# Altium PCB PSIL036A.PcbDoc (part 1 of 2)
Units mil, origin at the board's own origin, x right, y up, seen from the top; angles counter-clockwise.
Board outline 2820.01 x 3610.03 mil, 2 copper layers (Top Layer, Bottom Layer), stack 62 mil thick; 102 components, 95 nets, 316 pads, 73 vias.
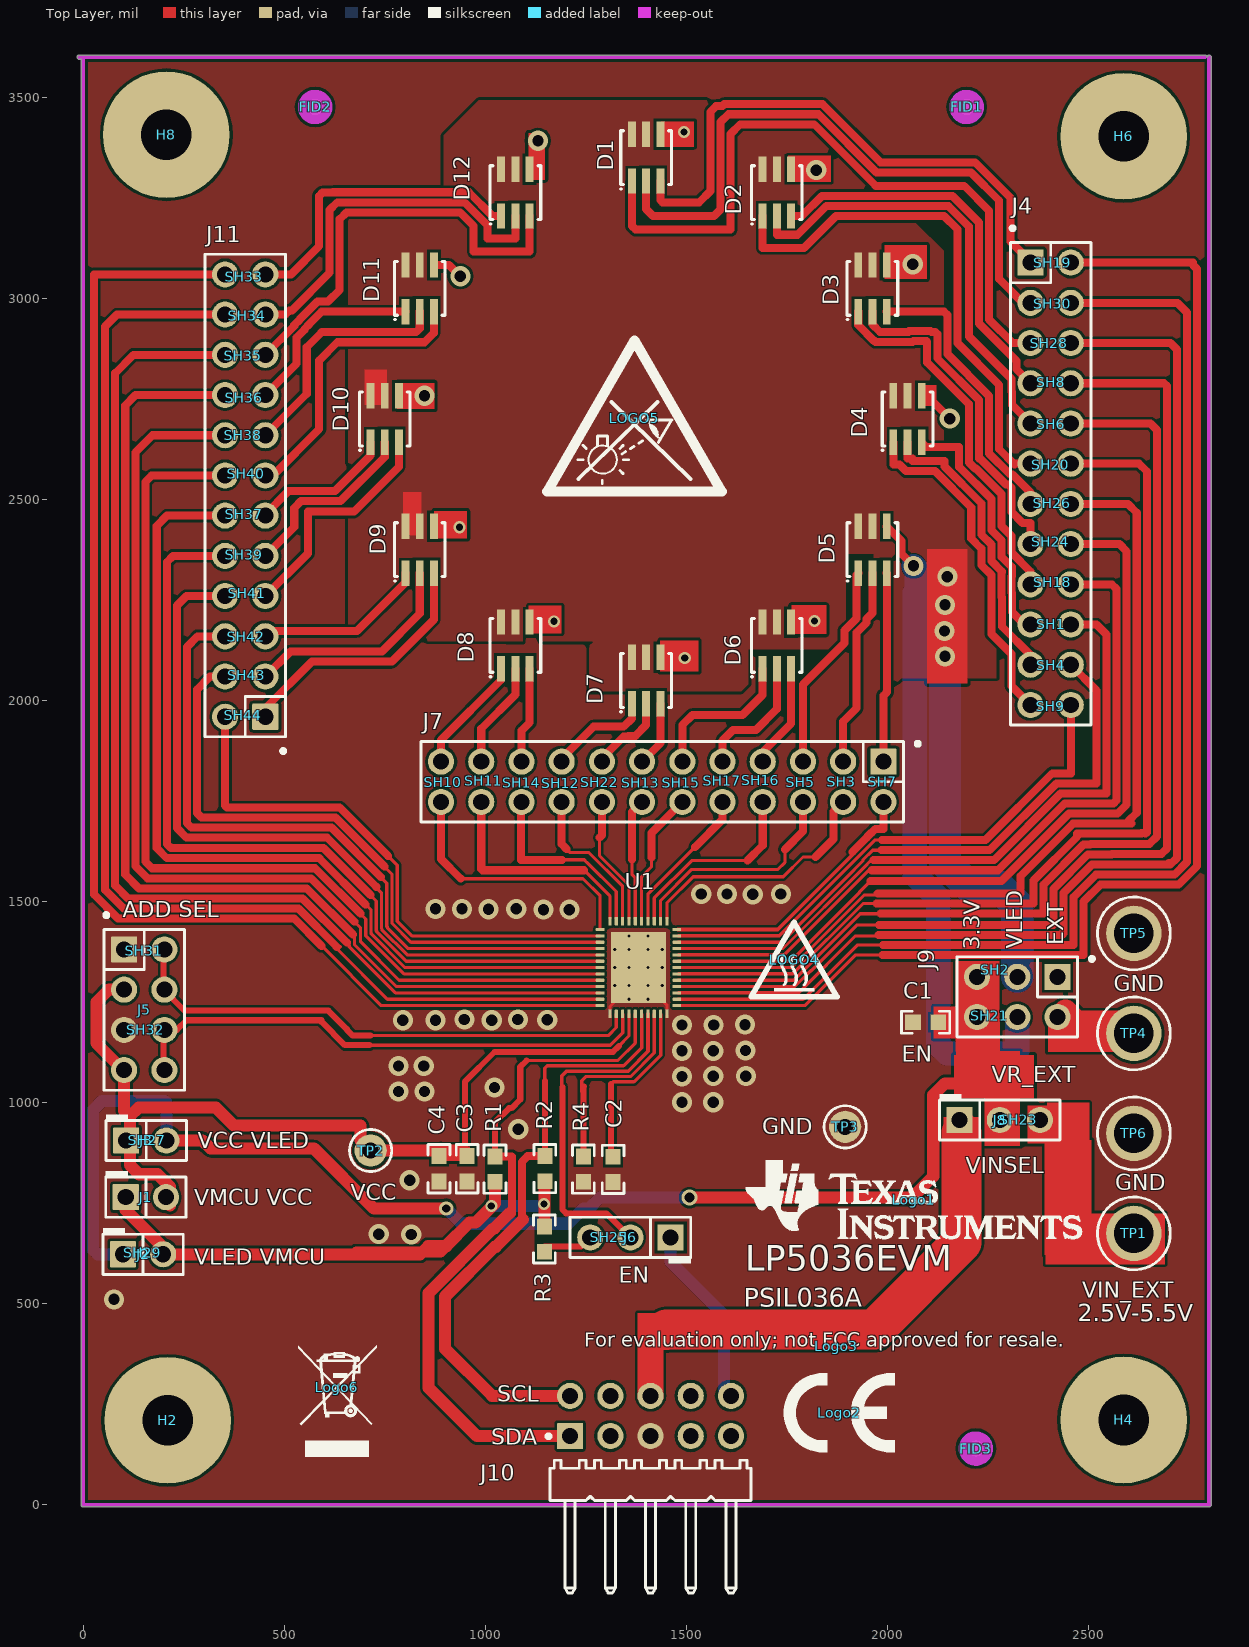
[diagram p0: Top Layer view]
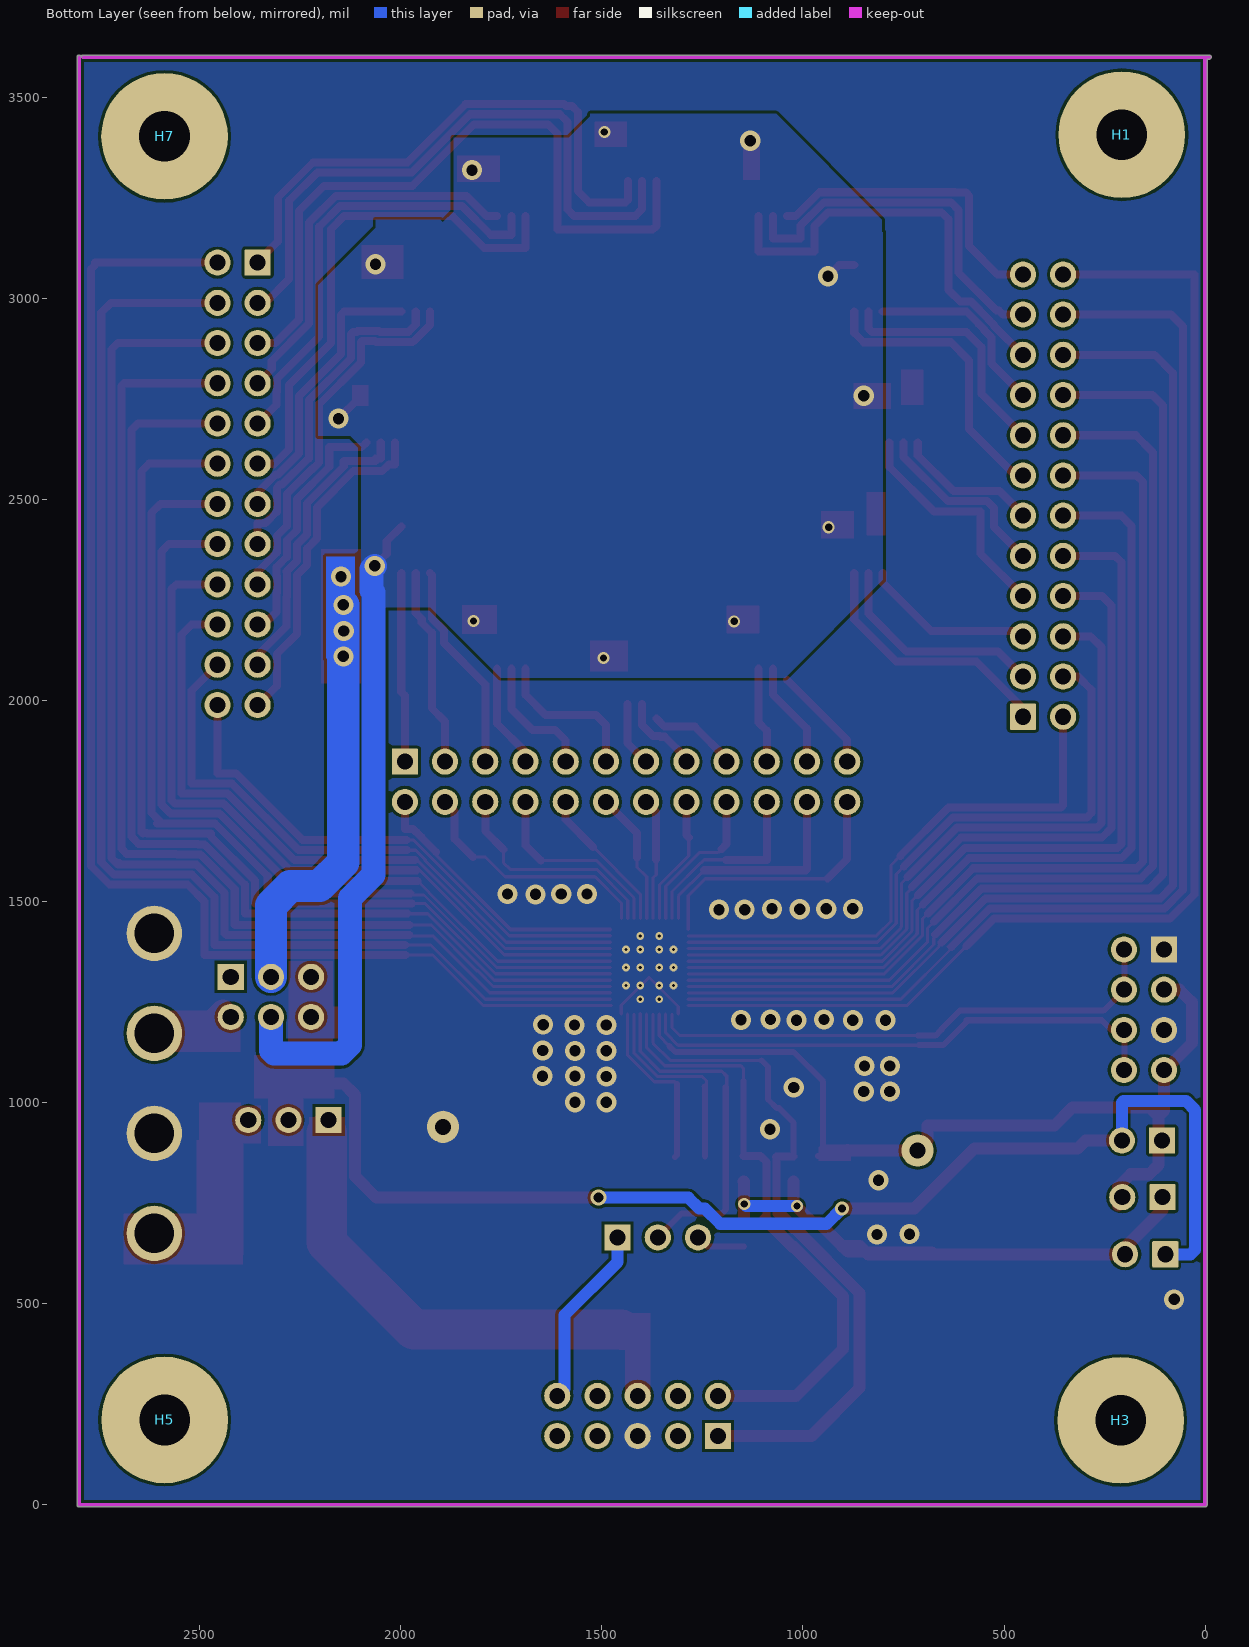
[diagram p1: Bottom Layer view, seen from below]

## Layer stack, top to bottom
Top Solder: solder mask 0.4, Solder Resist, Dk 3.5
Top Layer: signal copper 1.4
Dielectric1: core 59.2, FR-4, Dk 4.8
Bottom Layer: signal copper 1.4
Bottom Solder: solder mask 0.4, Solder Resist, Dk 3.5

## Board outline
-5.02,0 -5.02,3594.98 -10,3594.98 cw(c-10,3600) -10,3605.02 2790,3605.02 cw(c2790,3600) 2794.01,3603.02 2795.99,3603.02 ccw(c2800,3600) 2795,3600.39 ccw(c2790,3600) 2794.01,3603.02 2795.99,3603.02 cw(c2800,3600) 2805.02,3600 2805.02,0 cw(c2800,0) 2800,-5.01 0,-5.01 cw(c0,0)

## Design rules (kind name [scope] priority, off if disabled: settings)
AcuteAngle [All] p1: minimum=4.50000000000000E+0001 checktracksonly=FALSE
AssemblyTestPointUsage [All] p1: valid=2
Clearance Clearance_Keepouts [((IsTrack Or IsArc) And Not InPoly) And IsFree and IsKeepOut vs ((IsTrack Or IsArc) And Not InPoly) And IsFree and IsKeepOut] p1: gap=0 ignorepadtopadclearanceinfootprint=FALSE
Clearance Clearance_Poly [InPolygon] p2: gap=7 ignorepadtopadclearanceinfootprint=FALSE except(0: Arc-Hole Track-Hole SMDPad-Hole THPad-Hole Via-Hole Fill-Hole Poly-Hole Region-Hole Text-Hole)
Clearance [All] p3: gap=5 ignorepadtopadclearanceinfootprint=FALSE except(0: Arc-Hole Track-Hole SMDPad-Hole THPad-Hole Via-Hole Fill-Hole Poly-Hole Region-Hole Text-Hole)
ComponentClearance ComponentClearance_MountingHoles_FiducialMarks [InComponentClass('Mounting Holes') vs InComponentClass('FiducialMark')] p1: gap=50 collisioncheckmode=3 verticalgap=10 showdistances=FALSE
ComponentClearance [InComponent('Logo1') vs InComponent('Logo4')] p2: gap=0 collisioncheckmode=3 verticalgap=0 showdistances=FALSE
ComponentClearance ComponentClearance_Shunt [InComponentClass('Header') vs InComponentClass('Shunt')] p3: gap=0 collisioncheckmode=3 verticalgap=0 showdistances=FALSE
ComponentClearance ComponentClearance_Shunt_1 [InComponentClass('Header') vs InComponentClass('Shunt')] p4: gap=0 collisioncheckmode=3 verticalgap=0 showdistances=FALSE
ComponentClearance ComponentClearance_Logo [InComponentClass('Logo')] p5: gap=30 collisioncheckmode=3 verticalgap=10 showdistances=FALSE
ComponentClearance ComponentClearance_ScrewToNut [(HasFootprint('NY PMS 440 0025 PH')) vs (HasFootprint('Keystone_1902C'))] p6: gap=5 collisioncheckmode=3 verticalgap=10 showdistances=FALSE
ComponentClearance ComponentClearance_ScrewToNut_1 [(HasFootprint('NY PMS 440 0025 PH')) vs (HasFootprint('Keystone_2204'))] p7: gap=0 collisioncheckmode=3 verticalgap=0 showdistances=FALSE
ComponentClearance ComponentClearance_MountingHoles [InComponentClass('Mounting Holes')] p8: gap=20 collisioncheckmode=3 verticalgap=100000 showdistances=FALSE
ComponentClearance ComponentClearance_SmallPassives [HasFootprint('0201*') or HasFootprint('0402*') or HasFootprint('0508') or HasFootprint('0603*') or HasFootprint('0612') or HasFootprint('0805*') or HasFootprint('0815*') or HasFootprint('0830*') or HasFootprint('1206*') or HasFootprint('1210*') or HasFootprint('1808*') or HasFootprint('1812*') or HasFootprint('1825*') or HasFootprint('2010*') or HasFootprint('2220*') or HasFootprint('2225*') or HasFootprint('2512*') or HasFootprint('2728*') or HasFootprint('3518*') vs HasFootprint('0201*') or HasFootprint('0402*') or HasFootprint('0508') or HasFootprint('0603*') or HasFootprint('0612') or HasFootprint('0805*') or HasFootprint('0815*') or HasFootprint('0830*') or HasFootprint('1206*') or HasFootprint('1210*') or HasFootprint('1808*') or HasFootprint('1812*') or HasFootprint('1825*') or HasFootprint('2010*') or HasFootprint('2220*') or HasFootprint('2225*') or HasFootprint('2512*') or HasFootprint('2728*') or HasFootprint('3518*')] p9: gap=14.96 collisioncheckmode=3 verticalgap=10 showdistances=FALSE
ComponentClearance ComponentClearance_THtoSMT [IsThruComponent vs IsSMTComponent] p10: gap=40 collisioncheckmode=3 verticalgap=30 showdistances=FALSE
ComponentClearance ComponentClearance_THtoTH [IsThruComponent vs IsThruComponent] p11: gap=30 collisioncheckmode=3 verticalgap=30 showdistances=FALSE
ComponentClearance ComponentClearance_THtoTH_1 [InComponent('J8A') vs InComponent('J8B')] p12: gap=0 collisioncheckmode=3 verticalgap=0 showdistances=FALSE
ComponentClearance ComponentClearance_THtoTH_2 [InComponent('J8B') vs InComponent('J8C')] p13: gap=0 collisioncheckmode=3 verticalgap=0 showdistances=FALSE
DiffPairsRouting [All] p1: maxlimit=100 minlimit=10 mostfreqgap=10 toplayer_minwidth=15 toplayer_maxwidth=15 toplayer_prefwidth=15 bottomlayer_minwidth=15 bottomlayer_maxwidth=15 bottomlayer_prefwidth=15 maxuncoupledlength=1000
FabricationTestPointUsage TestPointUsage [All] p1: valid=2 allowmultiple=FALSE
FabricationTestpoint Testpoint [All] p1: side=3 testpointundercomponent=TRUE minsize=40 maxsize=100 preferedsize=60 minholesize=0 maxholesize=40 preferedholesize=32 testpointgrid=1 allowsidetop=TRUE allowsidebottom=TRUE usegrid=TRUE gridtolerance=0.01
FanoutControl Fanout_LCC [IsLCC] p1: bgadir=Out bgaviamode=Centered fanoutstyle=Auto fanoutdirection=Alternating viagrid=1 // Fanout_LCC (Default Rule)
FanoutControl Fanout_BGA [IsBGA] p2: bgadir=Out bgaviamode=Centered fanoutstyle=Auto fanoutdirection=Alternating viagrid=1 // Fanout_BGA (Default Rule)
FanoutControl Fanout_Default [All] p4: bgadir=Out bgaviamode=Centered fanoutstyle=Auto fanoutdirection=Alternating viagrid=1 // Fanout_Default (Default Rule)
FanoutControl Fanout_Small [(CompPinCount < 5)] p5: bgadir=Out bgaviamode=Centered fanoutstyle=Auto fanoutdirection=OutThenIn viagrid=1 // Fanout_Small (Default Rule)
HoleSize [All] p1: absolutevalues=TRUE maxlimit=251 minlimit=7.87 maxpercent=80.000 minpercent=20.000
MinimumAnnularRing MinimumAnnularRing_ThermalPadVias [IsVia and InAnyComponent] p1: minimumring=5.91
MinimumAnnularRing [All] p2: minimumring=6
MinimumSolderMaskSliver MinimumSolderMaskSliver_Logo [InComponentClass('Logo') vs InComponentClass('Logo')] p1: minsoldermaskwidth=0.7
MinimumSolderMaskSliver [All] p2: minsoldermaskwidth=3.94
PlaneClearance [InNet('SW')] p1: clearance=7
PlaneClearance PlaneClearance_1 [All] p2: clearance=20
PlaneConnect [InNet('SW')] p1: planeconnectstyle=Direct reliefexpansion=10 reliefentries=4 reliefconductorwidth=10 reliefairgap=10
PlaneConnect PlaneConnect_1 [All] p2: planeconnectstyle=Relief reliefexpansion=10 reliefentries=4 reliefconductorwidth=10 reliefairgap=10
PolygonConnect [InNet('SW') vs HasFootprint('DFE252012C')] p1: connectstyle=Direct reliefconductorwidth=10 reliefentries=4 polygonreliefangle="90 Angle" airgapwidth=10
PolygonConnect PolygonConnect_3 [InNet('GND') vs (HasFootprint('0603') OR HasFootprint('1210_280') OR IsVia)] p2: connectstyle=Direct reliefconductorwidth=10 reliefentries=4 polygonreliefangle="90 Angle" airgapwidth=10
PolygonConnect PolygonConnect_2 [InNet('VIN2') vs (HasFootprint('0603') OR HasFootprint('1210_280') OR IsVia)] p3: connectstyle=Direct reliefconductorwidth=10 reliefentries=4 polygonreliefangle="90 Angle" airgapwidth=10
PolygonConnect PolygonConnect_1 [All] p4: connectstyle=Direct reliefconductorwidth=30 reliefentries=4 polygonreliefangle="90 Angle" airgapwidth=10
RoutingVias ThermalPadVias [IsVia and InAnyComponent] p1: holewidth=7.87 width=19.68 viastyle="Through Hole" minholewidth=7.87 minwidth=19.68 maxholewidth=12.99 maxwidth=23.62
RoutingVias [All] p2: holewidth=16 width=34 viastyle="Through Hole" minholewidth=8 minwidth=20 maxholewidth=40 maxwidth=65
SilkToBoardRegionClearance [Not ((IsComment or IsDesignator) And (Hide <> 'False')) and not InRegion(1000,500,4000,800)] p1:
SilkToSilkClearance SilkToSilkClearance_Pb-FreeLogo [(HasFootprint('Pb-Free_Overlay_Medium') OR HasFootprint('Pb-Free_Overlay_Small')) vs (HasFootprint('Pb-Free_Overlay_Medium') OR HasFootprint('Pb-Free_Overlay_Small'))] p1: silktosilkclearance=3
SilkToSilkClearance [OnLayer('Bottom Overlay')] p2: silktosilkclearance=3
SilkToSilkClearance SilkToSilkClearance_1 [OnLayer('Top Overlay')] p3: silktosilkclearance=3
SilkToSolderMaskClearance SilkToComponentPadClearance_1 [IsPad and InAnycomponent vs OnLayer('Bottom Overlay')] p1: minsilkscreentomaskgap=0 clearancetoexposedcopper=TRUE
SilkToSolderMaskClearance SilkToComponentPadClearance_2 [IsVia vs OnLayer('Bottom Overlay')] p2: minsilkscreentomaskgap=0 clearancetoexposedcopper=TRUE
SilkToSolderMaskClearance SilkToComponentPadClearance [IsPad and InAnycomponent] p3: minsilkscreentomaskgap=4 clearancetoexposedcopper=TRUE
SilkToSolderMaskClearance "Silk to Solder Mask Opening" [All] p4: minsilkscreentomaskgap=4 clearancetoexposedcopper=FALSE
SolderMaskExpansion [All] p1: expansion=1.97
Width [All] p1: maxlimit=100 minlimit=6 preferedwidth=7 checkconnectedcopper=TRUE
14 further rules are at their usual default settings.

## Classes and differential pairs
component class FiducialMark: FID1 FID2 FID3
component class PSIL036A_Hardware: FID1 FID2 FID3 H1 H2 H3 H4 H5 H6 H7 H8 Logo1 Logo2 Logo3 LOGO4 LOGO5 Logo6 SH1 SH2 SH3 SH4 SH5 SH6 SH7 SH8 SH9 SH10 SH11 SH12 SH13 SH14 SH15 SH16 SH17 SH18 SH19 SH20 SH21 SH22 SH23 SH24 SH25 SH26 SH27 SH28 SH29 SH30 SH31 SH32 SH33 SH34 SH35 SH36 SH37 SH38 SH39 SH40 SH41 SH42 SH43 SH44 ZZ2 ZZ3 ZZ4
component class Header: J1 J2 J3 J4 J5 J6 J7 J8 J9 J10 J11 J15
component class PSIL036A_sh: C1 C2 C3 C4 D1 D2 D3 D4 D5 D6 D7 D8 D9 D10 D11 D12 J1 J2 J3 J4 J5 J6 J7 J8 J9 J10 J11 J15 J101 L100 R1 R2 R3 R4 R13 SH-J10 TP1 TP2 TP3 TP4 TP5 TP6 U1 VOUT
component class AssemblyNote: ZZ2 ZZ3 ZZ4
component class Logo: Logo1
component class Shunt: SH1 SH2 SH3 SH4 SH5 SH6 SH7 SH8 SH9 SH10 SH11 SH12 SH13 SH14 SH15 SH16 SH17 SH18 SH19 SH20 SH21 SH22 SH23 SH24 SH25 SH26 SH27 SH28 SH29 SH30 SH31 SH32 SH33 SH34 SH35 SH36 SH37 SH38 SH39 SH40 SH41 SH42 SH43 SH44 SH-J9
component class "Mounting Holes": H2 H4 H6 H8

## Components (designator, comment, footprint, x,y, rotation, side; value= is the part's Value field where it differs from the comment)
C1 "C1608JB0J106K080AB" 0603 2095,1200 r180 top value=10uF
C2 "06033C105KAT2A" 0603 1318,834 r270 top value=1uF
C3 "06033C105KAT2A" 0603 955,835.7 r270 top value=1uF
C4 "0603YC104JAT2A" 0603 885,835.7 r270 top value=0.1uF
D1 "ASMT-YTC2-0AA02" Avago_ASMT-YTC2-0AA02 1400,3350 r90 top value=Rgb
D2 "ASMT-YTC2-0AA02" Avago_ASMT-YTC2-0AA02 1725,3262.9 r90 top value=Rgb
D3 "ASMT-YTC2-0AA02" Avago_ASMT-YTC2-0AA02 1962.9,3025 r90 top value=Rgb
D4 "ASMT-YTC2-0AA02" Avago_ASMT-YTC2-0AA02 2050,2700 r90 top value=Rgb
D5 "ASMT-YTC2-0AA02" Avago_ASMT-YTC2-0AA02 1962.9,2375 r90 top value=Rgb
D6 "ASMT-YTC2-0AA02" Avago_ASMT-YTC2-0AA02 1725,2137.1 r90 top value=Rgb
D7 "ASMT-YTC2-0AA02" Avago_ASMT-YTC2-0AA02 1400,2050 r90 top value=Rgb
D8 "ASMT-YTC2-0AA02" Avago_ASMT-YTC2-0AA02 1075,2137.1 r90 top value=Rgb
D9 "ASMT-YTC2-0AA02" Avago_ASMT-YTC2-0AA02 837.1,2375 r90 top value=Rgb
D10 "ASMT-YTC2-0AA02" Avago_ASMT-YTC2-0AA02 750,2700 r90 top value=Rgb
D11 "ASMT-YTC2-0AA02" Avago_ASMT-YTC2-0AA02 837.1,3025 r90 top value=Rgb
D12 "ASMT-YTC2-0AA02" Avago_ASMT-YTC2-0AA02 1075,3262.9 r90 top value=Rgb
FID1 "Fiducial" Fiducial10-20 2197,3476 r0 top
FID2 "Fiducial" Fiducial10-20 577,3476 r0 top
FID3 "Fiducial" Fiducial10-20 2220,140 r0 top
H1 "1902C" Keystone_1902C 207,3407 r180 bottom
H2 "NY PMS 440 0025 PH" "NY PMS 440 0025 PH" 210,210 r0 top
H3 "1902C" Keystone_1902C 210,210 r180 bottom
H4 "NY PMS 440 0025 PH" "NY PMS 440 0025 PH" 2587.47,211 r0 top
H5 "1902C" Keystone_1902C 2587.47,211 r0 bottom
H6 "NY PMS 440 0025 PH" "NY PMS 440 0025 PH" 2587.53,3403 r0 top
H7 "1902C" Keystone_1902C 2587.53,3403 r180 bottom
H8 "NY PMS 440 0025 PH" "NY PMS 440 0025 PH" 207,3407 r0 top
J1 "VMCU VCC" TSW-102-07-G-S 156,765 r0 top
J2 "VLED VMCU" TSW-102-07-G-S 149,623 r0 top
J3 "VCC VLED" TSW-102-07-G-S 157,906 r0 top
J4 "TSW-112-07-G-D" TSW-112-07-G-D 2405.99,2539 r270 top
J5 "ADD SEL" TSW-104-07-G-D 152,1231 r270 top
J6 "EN" TSW-103-07-G-S 1361,665 r180 top
J7 "TSW-112-07-G-D" TSW-112-07-G-D 1440,1798 r180 top
J8 "VINSEL" TSW-103-07-G-S 2279.51,956.91 r0 top
J9 "" TSW-103-07-G-D 2323,1263 r180 top
J10 "TSW-105-08-G-D-RA" Samtec_TSW-105-08-G-D-RA 1411,221 r0 top
J11 "TSW-112-07-G-D" TSW-112-07-G-D 403,2509.76 r90 top
Logo1 "Texas Instruments" TI_Stacked_Overlay_Small 2065.78,758.88 r0 top
Logo2 "CE Mark" CE_Mark_5mm 1880,229 r0 top (schematic designator LOGO2)
Logo3 "FCC disclaimer" FCC_disclaimer 1873,394 r0 top
LOGO4 "CAUTION HOT SURFACE" IEC_HotSurface_Small 1768,1356 r0 top
LOGO5 "LED WARNING" LED_Warning 1371,2702 r0 top
Logo6 "WEEE logo" WEEE_Minimum 631,292 r0 top
R1 "CRCW06034K70JNEA" 0603 1024,835 r270 top value=4.7k
R2 "CRCW06034K70JNEA" 0603 1148,836 r270 top value=4.7k
R3 "CRCW06034K70JNEA" 0603 1147,661 r90 top value=4.7k
R4 "RC0603FR-073K57L" 0603 1244,835 r90 top value=3.57k
SH1 "" SPC02SYAN 2408,2190 r0 top value=1x2
SH2 "" SPC02SYAN 2268,1330 r0 top value=1x2
SH3 "" SPC02SYAN 1886,1798 r270 top value=1x2
SH4 "" SPC02SYAN 2408,2088 r0 top value=1x2
SH5 "" SPC02SYAN 1784,1797 r270 top value=1x2
SH6 "" SPC02SYAN 2408,2687 r0 top value=1x2
SH7 "" SPC02SYAN 1988,1798 r270 top value=1x2
SH8 "" SPC02SYAN 2408,2792 r0 top value=1x2
SH9 "" SPC02SYAN 2406,1986 r0 top value=1x2
SH10 "" SPC02SYAN 895,1797 r90 top value=1x2
SH11 "" SPC02SYAN 996,1800 r90 top value=1x2
SH12 "" SPC02SYAN 1188,1794 r90 top value=1x2
SH13 "" SPC02SYAN 1387,1796 r90 top value=1x2
SH14 "" SPC02SYAN 1091,1795 r90 top value=1x2
SH15 "" SPC02SYAN 1487,1795 r90 top value=1x2
SH16 "" SPC02SYAN 1685,1802 r90 top value=1x2
SH17 "" SPC02SYAN 1589,1801 r90 top value=1x2
SH18 "" SPC02SYAN 2411,2294 r180 top value=1x2
SH19 "" SPC02SYAN 2411,3089 r180 top value=1x2
SH20 "" SPC02SYAN 2406,2586 r180 top value=1x2
SH21 "" SPC02SYAN 2254,1216 r180 top value=1x2
SH22 "" SPC02SYAN 1285,1797 r90 top value=1x2
SH23 "" SPC02SYAN 2327,958 r180 top value=1x2
SH24 "" SPC02SYAN 2406,2395 r180 top value=1x2
SH25 "" SPC02SYAN 1308,665 r180 top value=1x2
SH26 "" SPC02SYAN 2410,2490 r180 top value=1x2
SH27 "" SPC02SYAN 160,907 r180 top value=1x2
SH28 "" SPC02SYAN 2403,2889 r180 top value=1x2
SH29 "" SPC02SYAN 148,627 r180 top value=1x2
SH30 "" SPC02SYAN 2411,2987 r180 top value=1x2
SH31 "" SPC02SYAN 152,1378 r180 top value=1x2
SH32 "" SPC02SYAN 156,1181 r180 top value=1x2
SH33 "" SPC02SYAN 401,3054 r180 top value=1x2
SH34 "" SPC02SYAN 408,2957 r180 top value=1x2
SH35 "" SPC02SYAN 398,2857 r180 top value=1x2
SH36 "" SPC02SYAN 401,2753 r180 top value=1x2
SH37 "" SPC02SYAN 401,2463 r180 top value=1x2
SH38 "" SPC02SYAN 398,2660 r180 top value=1x2
SH39 "" SPC02SYAN 401,2363 r180 top value=1x2
SH40 "" SPC02SYAN 405,2564 r180 top value=1x2
SH41 "" SPC02SYAN 408,2267 r180 top value=1x2
SH42 "" SPC02SYAN 405,2159 r180 top value=1x2
SH43 "" SPC02SYAN 407,2063 r180 top value=1x2
SH44 "" SPC02SYAN 398,1963 r180 top value=1x2
TP1 "VIN_EXT" Keystone1502-2 2613,675 r0 top
TP2 "VCC" Keystone5000 715,881 r90 top
TP3 "GND" Keystone5001 1895,940 r0 top
TP4 "VR_EXT" Keystone1502-2 2613,1172.33 r0 top
TP5 "GND" Keystone1502-2 2613,1421 r0 top
TP6 "GND" Keystone1502-2 2613,923.67 r0 top
U1 "LP5036RJVR" RJV0046A 1381,1336 r180 top
ZZ2 "These assemblies are ESD sensitive, ESD precautions shall be observed." AssemblyNote -285.77,3783.99 r0 top
ZZ3 "These assemblies must be clean and free from flux and all contaminants. Use of no clean flux is not acceptable." AssemblyNote -285.77,3683.99 r0 top
ZZ4 "These assemblies must comply with workmanship standards IPC-A-610 Class 2, unless otherwise specified." AssemblyNote -293,3885 r0 top

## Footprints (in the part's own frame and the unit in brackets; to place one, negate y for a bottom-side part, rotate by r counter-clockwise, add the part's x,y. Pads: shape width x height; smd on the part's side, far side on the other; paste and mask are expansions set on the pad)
0603 [mm] "0603 from SM-752 data"
  rect 1x0.95 smd: 1(-0.8,0) 2(0.8,0)
  silkscreen extent -1.52,-0.69 1.52,0.69, body extent -0.87,-0.47 0.87,0.47, height 1
AssemblyNote [mil] "Assembly Note"
Avago_ASMT-YTC2-0AA02 [mm] "Avago"
  rect 1.6x0.5 smd: 1(-1.475,0.9) 2(-1.475,0) 3(-1.475,-0.9) 4(1.475,-0.9) 5(1.475,0) 6(1.475,0.9)
  silkscreen extent -1.97,-1.6 1.7,1.6, body extent -1.7,-1.6 1.7,1.6, height 2
CE_Mark_5mm [mil] "Minimum text height for CE Mark"
  silkscreen extent -138,-98 138,98
FCC_disclaimer [mil]
Fiducial10-20 [mm]
  round 1 smd mask+0.5: 1(0,0)
  Top Layer keep-out circle w1.178: c0,0 r0.5
IEC_HotSurface_Small [mil]
  silkscreen extent -107,-93 107,92
Keystone1502-2 [mm] "Double Turret"
  round 3.5 hole 2.5: 1(0,0)
  silkscreen extent -2.3,-2.3 2.3,2.3, body extent -1.6,-1.6 1.59,1.6, height 5.62
Keystone5000 [mil] "For Keystone 500x miniature loop terminals"
  round 80 hole 40: 1(0,0)
  silkscreen extent -52,-52 52,52, body extent -49,-49 49,49, height 182
Keystone5001 [mil] "For Keystone 500x miniature loop terminals"
  round 80 hole 40: 1(0,0)
  silkscreen extent -52,-52 52,52, body extent -49,-49 49,49, height 182
Keystone_1902C [mil] "Hex Standoff, 4-40 threaded, nylon"
  round 1 on Mech4: 0(0,0)
  body extent -145,-126 146,126, height 501
LED_Warning [mil]
  silkscreen extent -217,-182 217,193
"NY PMS 440 0025 PH" [mm] "4-40 nylon screw and mounting hole"
  round 8 hole 3.2: 1(0,0)
  body extent -3.3,-3.3 3.3,3.3, height 2.69
RJV0046A [mm] "QFN, 46-Leads, Body 5x6mm, Pitch 0.4mm"
  rrect50% 0.55x0.2 smd: 1(-2.425,2.4) 2(-2.425,2) 3(-2.425,1.6) 4(-2.425,1.2) 5(-2.425,0.8) 6(-2.425,0.4) 7(-2.425,0) 8(-2.425,-0.4) 9(-2.425,-0.8) 10(-2.425,-1.2) 11(-2.425,-1.6) 12(-2.425,-2) 13(-2.425,-2.4) 24(2.425,-2.4) 25(2.425,-2) 26(2.425,-1.6) 27(2.425,-1.2) 28(2.425,-0.8) 29(2.425,-0.4) 30(2.425,0) 31(2.425,0.4) 32(2.425,0.8) 33(2.425,1.2) 34(2.425,1.6) 35(2.425,2) 36(2.425,2.4)
  rrect50% 0.2x0.55 smd: 14(-1.8,-2.925) 15(-1.4,-2.925) 16(-1,-2.925) 17(-0.6,-2.925) 18(-0.2,-2.925) 19(0.2,-2.925) 20(0.6,-2.925) 21(1,-2.925) 22(1.4,-2.925) 23(1.8,-2.925) 37(1.8,2.925) 38(1.4,2.925) 39(1,2.925) 40(0.6,2.925) 41(0.2,2.925) 42(-0.2,2.925) 43(-0.6,2.925) 44(-1,2.925) 45(-1.4,2.925) 46(-1.8,2.925)
  rrect3% 3.5x4.5 smd paste-4.5: 47(0,0)
  rrect11% 1x0.94 on Top Paste: ""(-1.2,1.71) ""(-1.2,-0.57) ""(-1.2,0.57) ""(-1.2,-1.71) ""(0,1.71) ""(0,0.57) ""(0,-0.57) ""(0,-1.71) ""(1.2,1.71) ""(1.2,-0.57) ""(1.2,0.57) ""(1.2,-1.71)
  body extent -2.5,-3 2.5,3, height 1
Samtec_TSW-105-08-G-D-RA [mm] "Samtec Right Angle Header"
  rrect6% 1.65x1.65 / inner rect 1.65x1.65 / far side rect 1.65x1.65 hole 1: 1(-5.08,-1.27)
  round 1.65 hole 1: 2(-5.08,1.27) 3(-2.54,-1.27) 4(-2.54,1.27) 5(0,-1.27) 6(0,1.27) 7(2.54,-1.27) 8(2.54,1.27) 9(5.08,-1.27) 10(5.08,1.27)
  silkscreen extent -6.57,-11.18 6.35,-1.16, body extent -6.35,-11.18 6.35,1.59, height 5.64
SPC02SYAN [mil] "SULLINS"
  round 1 on Mech3: 0(0,0)
  body extent -98,-47 99,47, height 366
TI_Stacked_Overlay_Small [mil]
  silkscreen extent -418,-98 418,98
TSW-102-07-G-S [mm] "Samtec 100mil, 1x2, 230 mil above insulator"
  rrect6% 1.65x1.65 hole 1.016: 1(-1.27,0)
  round 1.65 hole 1.016: 2(1.27,0)
  silkscreen extent -2.54,-1.27 2.54,1.65, body extent -2.54,-1.27 2.54,1.27, height 8.38
TSW-103-07-G-D [mm] "Samtec 100mil, 2x3, 230 mil above insulator"
  rect 1.65x1.65 hole 1.016: 1(-2.54,-1.27)
  round 1.65 hole 1.016: 2(-2.54,1.27) 3(0,-1.27) 4(0,1.27) 5(2.54,-1.27) 6(2.54,1.27)
  silkscreen extent -4.84,-2.54 3.81,2.54, body extent -3.81,-2.54 3.81,2.54, height 8.38
TSW-103-07-G-S [mm] "Samtec 100mil, 1x3, 230 mil above insulator"
  rect 1.65x1.65 hole 1.016: 1(-2.54,0)
  round 1.65 hole 1.016: 2(0,0) 3(2.54,0)
  silkscreen extent -3.81,-1.27 3.81,1.65, body extent -3.81,-1.27 3.81,1.27, height 8.38
TSW-104-07-G-D [mm] "Samtec 100mil, 2x4, 230 mil above insulator"
  rrect6% 1.65x1.65 hole 1.016: 1(-3.81,-1.27)
  round 1.65 hole 1.016: 2(-3.81,1.27) 3(-1.27,-1.27) 4(-1.27,1.27) 5(1.27,-1.27) 6(1.27,1.27) 7(3.81,-1.27) 8(3.81,1.27)
  silkscreen extent -6.1,-2.54 5.08,2.54, body extent -5.08,-2.54 5.08,2.54, height 8.38
TSW-112-07-G-D [mm] "Samtec 100mil, 2x12, 230 mil above insulator"
  rrect6% 1.65x1.65 hole 1.016: 1(-13.97,-1.27)
  round 1.65 hole 1.016: 2(-13.97,1.27) 3(-11.43,-1.27) 4(-11.43,1.27) 5(-8.89,-1.27) 6(-8.89,1.27) 7(-6.35,-1.27) 8(-6.35,1.27) 9(-3.81,-1.27) 10(-3.81,1.27) 11(-1.27,-1.27) 12(-1.27,1.27) 13(1.27,-1.27) 14(1.27,1.27) 15(3.81,-1.27) 16(3.81,1.27) 17(6.35,-1.27) 18(6.35,1.27) 19(8.89,-1.27) 20(8.89,1.27) 21(11.43,-1.27) 22(11.43,1.27) 23(13.97,-1.27) 24(13.97,1.27)
  silkscreen extent -16.26,-2.54 15.24,2.54, body extent -15.24,-2.54 15.24,2.54, height 8.38
WEEE_Minimum [mil] "WEEElie bin"
  silkscreen extent -95,-172 99,104

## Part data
C1: "CAP, CERM, 10 μF, 6.3 V, +/- 10%, JB, 0603", Cap_Case=0603, Manufacturer=TDK, Supplier Part Number 1=445-11185-1-ND, TempCo=JB, Tolerance_%=10, Value1=Unknown, Value2=6.3V, ValueDisplayed=10μF
C2 C3: "CAP, CERM, 1 μF, 25 V,+/- 10%, X7R, 0603", Cap_Case=0603, Manufacturer=AVX, Supplier Part Number 1=478-10046-1-ND, TempCo=X7R, Tolerance_%=10, Value2=25V, ValueDisplayed=1μF
C4: "CAP, CERM, 0.1 μF, 16 V,+/- 5%, X7R, 0603", Cap_Case=0603, Manufacturer=AVX, Supplier Part Number 1=478-3726-1-ND, TempCo=X7R, Tolerance_%=5, Value1="0.039 ohm", Value2=16V, ValueDisplayed=0.1μF
D1 D2 D3 D4 D5 D6 D7 D8 D9 D10 D11 D12: "LED, Rgb, SMD", Color=RGB, Manufacturer=Avago, Supplier Part Number 1=516-2513-1-ND, Value1=W, Value2=3.2V
FID1 FID2 FID3: "Fiducial mark.  There is nothing to buy or mount.", Manufacturer=N/A
H1 H3 H5 H7: "Standoff, Hex, 0.5\"L #4-40 Nylon", Manufacturer=Keystone, Supplier Part Number 1=36-1902C-ND
H2 H4 H6 H8: "Machine Screw, Round, #4-40 x 1/4, Nylon, Philips panhead", DigiKeyPartNumber=H542-ND, Manufacturer="B&F Fastener Supply"
J1 J2 J3: library part TSW-102-07-G-S, "Header, 100mil, 2x1, Gold, TH", Color=Black, Current_A=6.3, Manufacturer=Samtec, Supplier Part Number 1=SAM1029-02-ND, Voltage_V=550
J4 J7 J11: "Header, 100mil, 12x2, Gold, TH", Color=Black, Current_A=6.3, Manufacturer=Samtec, Supplier Part Number 1=SAM1028-12-ND, Voltage_V=550
J5: library part TSW-104-07-G-D, "Header, 100mil, 4x2, Gold, TH", Color=Black, Current_A=6.3, Manufacturer=Samtec, Supplier Part Number 1=SAM1028-04-ND, Voltage_V=550
J6 J8: library part TSW-103-07-G-S, "Header, 100mil, 3x1, Gold, TH", Color=Black, Current_A=6.3, Manufacturer=Samtec, Supplier Part Number 1=SAM1029-03-ND, Voltage_V=550
J9: library part TSW-103-07-G-D, "Header, 100mil, 3x2, Gold, TH", Color=Black, Current_A=6.3, Manufacturer=Samtec, Supplier Part Number 1=SAM1028-03-ND, Voltage_V=550
J10: "Header, 100mil, 5x2, Gold, R/A, TH", Color=Black, Current_A=6.3, Manufacturer=Samtec, Supplier Part Number 1=SAM1037-05-ND, Voltage_V=550
Logo1: library part TI_Logo, "Texas Instrument Corporate Signature"
Logo2: library part CMP-0074844-1
Logo3: library part FCC_disclaimer, "FCC_disclaimer"
LOGO4: library part IEC_HotSurface, "IEC 61010-1 Hot Surface Warning"
LOGO5: library part LED_Warning, "LED Warning Symbol"
Logo6: library part CMP-0074769-1
R1 R2 R3: "RES, 4.7 k, 5%, 0.1 W, 0603", Manufacturer=Vishay-Dale, Power_W=0.1, Supplier Part Number 1=541-4.7KGCT-ND, TempCo="200 ppm/C", Tolerance_%=5, Value1=5%, Value2=0.1W, Value_Code=4k70, ValueDisplayed=4.7k
R4: "RES, 3.57 k, 1%, 0.1 W, 0603", Manufacturer="Yageo America", Power_W=0.1, Supplier Part Number 1=311-3.57KHRCT-ND, TempCo="200 ppm/C", Tolerance_%=1, Value1=1%, Value2=0.1W, Value_Code=3k57, ValueDisplayed=3.57k
SH1 SH2 SH3 SH4 SH5 SH6 SH7 SH8 SH9 SH10 SH11 SH12 SH13 SH14 SH15 SH16 SH17 SH18 SH19 SH20 SH21 SH22 SH23 SH24 SH25 SH26 SH27 SH28 SH29 SH30 SH31 SH32 SH33 SH34 SH35 SH36 SH37 SH38 SH39 SH40 SH41 SH42 SH43 SH44: library part SPC02SYAN, "Shunt, 100mil, Flash Gold, Black", Manufacturer="Sullins Connector Solutions", Supplier Part Number 1=S9001-ND
TP1 TP4 TP5 TP6: library part 1502-2, "Terminal, Turret, TH, Double", Manufacturer=Keystone, Supplier Part Number 1=36-1502-2-ND
TP2: library part 5000, "Test Point, Miniature, Red, TH", Color=Red, Manufacturer=Keystone, Supplier Part Number 1=36-5000-ND
TP3: library part 5001, "Test Point, Miniature, Black, TH", Color=Black, Manufacturer=Keystone, Supplier Part Number 1=36-5001-ND
U1: library part CMP-0079213-2, "36-Channel 12-Bit PWM Ultralow Quiescent Current I2C RGB LED Driver, RJV0046A (VQFN-46)", Alternate Manufacturer="Texas Instruments"
ZZ2 ZZ3 ZZ4: library part AssemblyNote, Alternate Manufacturer=-

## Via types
v1: diameter 50, hole 28, Top Layer to Bottom Layer, 48 vias
v2: diameter 19.68, hole 7.87, Top Layer to Bottom Layer, 16 vias
v3: diameter 30, hole 18, Top Layer to Bottom Layer, 7 vias
v4: diameter 35, hole 20, Top Layer to Bottom Layer, 1 vias
v5: diameter 40, hole 25, Top Layer to Bottom Layer, 1 vias

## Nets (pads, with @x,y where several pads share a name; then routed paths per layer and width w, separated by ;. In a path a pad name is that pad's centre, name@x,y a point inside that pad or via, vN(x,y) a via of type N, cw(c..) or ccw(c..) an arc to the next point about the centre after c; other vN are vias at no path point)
ADDR0: J5.2 J5.4 U1.38 | length 1316.5
  Top Layer w8: 714,1166.88 1305.88,1166.88 1325.88,1186.88 U1.38@1325.88,1220.84
  Top Layer w15: J5.2@200,1381 200,1281 252.12,1228.88 610,1228.88 655.88,1183 655.88,1181.12 670.12,1166.88 714,1166.88
ADDR1: J5.6 J5.8 U1.39 | length 1339.5
  Top Layer w8: 712,1143 1311,1143 1341.63,1173.63 U1.39@1341.63,1220.84
  Top Layer w15: J5.8@200,1081 200,1181 233,1181 257,1205 593,1205 593,1201 651,1143 712,1143
EN: J6.1 J10.10 | length 467.6
  Bottom Layer w30: J6.1@1461,665 1461,604 1593.5,471.5 1593.5,288.5 J10.10@1611,271 ; J6.1@1469.32,664.51 J6.1@1470,676
GND: C1.2 C2.2 C3.2 C4.2 J5.1 J5.5 J10.5 R4.1 TP3.1 TP5.1 TP6.1 U1.37 U1.46 U1.47 | length 237.9
  Top Layer w8: U1.37@1310.13,1220.84 1310.13,1239.13 U1.47@1381,1310 ; U1.47@1382.5,1311.5 1451.87,1242.13 U1.46@1451.87,1220.84
  other v1: 77,511 816,672 735,673 812,807 1082,934 1489,1001 1567,1001 784,1028 849,1028 1023,1038 1489,1065 1567,1066 1648,1066 784,1091 847,1091 1489,1129 1567,1129 1647,1130 1489,1193 1568,1193 1646,1194 795,1205 876,1205 1016,1205 1154,1206 948,1207 1081,1207 1145,1480 1209,1480 1008,1481 876,1482 942,1482 1077,1482 1665,1518 1537,1519 1601,1519 1735,1519
  other v2: 1357.38,1257.26 1404.62,1257.26 1321.94,1291.12 1357.38,1291.12 1404.62,1291.12 1440.06,1291.12 1321.94,1336 1357.38,1336 1404.62,1336 1440.06,1336 1321.94,1380.88 1357.38,1380.88 1404.62,1380.88 1440.06,1380.88 1357.38,1414.74 1404.62,1414.74
GPIO2/SPI(SCLK): J10.3
GPIO3/PWM2: J10.4
GPIO4/SPI(SIMO)/UART(TXD): J10.7
GPIO5/SPI(SOMI)/UART(RXD): J10.8
GPIO6/PWM1/SPI(CS): J10.9
IN_EN: J6.2 U1.43 | length 864.1
  Top Layer w9: 1192,1039 1190,1041 1190,1066.5 1202,1078.5 1355.5,1078.5 1404.62,1127.62 U1.43@1404.62,1220.84
  Top Layer w15: 1192,1039 1192,733.99 1200.99,725 1301,725 J6.2@1361,665
IREF: R4.2 U1.44 | length 513.2
  Top Layer w8: 1244,1023 1240,1027 1240,1055 1250,1065 1361.09,1065 1420.37,1124.28 U1.44@1420.37,1220.84
  Top Layer w15: R4.2@1244,866.5 1244,1023 1244,1039 1245,1040
LB0: D1.3 J4.1 | length 1415.1
  Top Layer w20: D1.3@1435.43,3291.93 1435.43,3244.57 1441,3239 1532,3239 1560,3267 1560,3464 1574.18,3478.18 1589.47,3478.18 1594.29,3483 1838.71,3483 1983.21,3338.5 2217.86,3338.5 2306,3250.36 2306,3141.83 2355.99,3091.84 J4.1@2355.99,3089
LB1: D1.2 J4.3 | length 1573.6
  Top Layer w20: D1.2@1400,3291.93 1400,3222 1417,3205 1569,3205 1585,3221 1585,3438.36 1604.64,3458 1828.36,3458 1972.86,3313.5 2207.5,3313.5 2278,3243 2278,3048 2337,2989 J4.3@2355.99,2989
LB2: D1.1 J4.5 | length 1738.4
  Top Layer w20: D1.1@1364.57,3291.93 1364.57,3180.43 1374,3171 1610,3171 1610,3409 1634,3433 1818,3433 1971,3280 2191,3280 2253,3218 2253,2947.71 2311.72,2889 J4.5@2355.99,2889
LB3: D2.3 J4.7 | length 968.5
  Top Layer w20: D2.3@1760.43,3204.83 1786.83,3204.83 1837,3255 2161.66,3255 2228,3188.66 2228,2937.35 2321,2844.35 2321,2823.99 J4.7@2355.99,2789
LB4: D2.2 J4.9 | length 1128.1
  Top Layer w20: D2.2@1725,3204.83 1725,3158.33 1776.49,3158.33 1848,3229.84 2151.46,3229.84 2203,3178.3 2203,2905 2308.51,2799.49 2308.51,2768.27 2309.57,2767.21 2309.57,2735.41 J4.9@2355.99,2689
LB5: D2.1 J4.11 | length 1294.9
  Top Layer w20: D2.1@1689.57,3204.83 1689.57,3125.43 1792.59,3125.43 1872,3204.84 2141.1,3204.84 2174,3171.95 2174,2889 2278,2785 2278,2625 2316,2587 2318,2589 J4.11@2355.99,2589
LB6: D3.3 J4.13 | length 712.8
  Top Layer w20: D3.3@1998.33,2966.93 2141.07,2966.93 2149,2959 2149,2861.64 2253,2757.64 2253,2614.64 2305.64,2562 2311,2562 2355.99,2517.01 J4.13@2355.99,2489
LB7: D3.2 J4.15 | length 839.3
  Top Layer w20: D3.2@1962.9,2966.93 1962.9,2935.1 1981,2917 2052.07,2917 2054.07,2919 2107.36,2919 2109.36,2917 2119,2917 2124,2912 2124,2851.29 2228,2747.29 2228,2602 2230.29,2602 2295.29,2537 2300.64,2537 2308.51,2529.13 2308.51,2469.33 2336.33,2441.51 2355.99,2441.51 J4.15@2355.99,2389
LB8: D3.1 J4.17 | length 934.6
  Top Layer w20: D3.1@1927.47,2966.93 1927.47,2933.53 1967,2894 1968.64,2894 1970.64,2892 2062.43,2892 2064.43,2894 2097,2894 2099,2892 2099,2840.93 2203,2736.93 2203,2591.64 2217.64,2577 2219.93,2577 2283.51,2513.42 2283.51,2433.97 2308.51,2408.97 2308.51,2367.86 2355.99,2320.38 J4.17@2355.99,2289
LB9: D4.3 J4.19 | length 621.8
  Top Layer w20: D4.3@2085.43,2641.93 2097.36,2630 2178,2630 2178,2581.29 2258.51,2500.78 2258.51,2423.62 2283.51,2398.62 2283.51,2357.51 2309.43,2331.6 2309.43,2309.57 2308.51,2308.66 2308.51,2268.42 2309.43,2267.5 2309.43,2220.57 2341,2189 J4.19@2355.99,2189
LB10: D4.2 J4.21 | length 735.1
  Top Layer w20: D4.2@2050,2641.93 2050,2602 2062.81,2602 2062.81,2595.43 2101.49,2595.43 2102.06,2596 2142,2596 2142,2581.93 2233.51,2490.42 2233.51,2413 2258.51,2388 2258.51,2347.15 2284.43,2321.24 2284.43,2319.93 2283.51,2319.02 2283.51,2257.15 2284.43,2256.24 2284.43,2184.57 2355.99,2113.01 J4.21@2355.99,2089
LB11: D4.1 J4.23 | length 845.3
  Top Layer w20: D4.1@2014.57,2641.93 2014.57,2587 2029.64,2587 2046.21,2570.43 2118.15,2570.43 2208.51,2480.07 2208.51,2402.64 2233.51,2377.64 2233.51,2336.8 2258.51,2311.8 2258.51,2165.49 2308.51,2115.49 2308.51,2036.48 J4.23@2355.99,1989
LB12: D5.3 J7.1 | length 472.9
  Top Layer w20: J7.1@1990,1848 1990,2012 1999,2021 1999,2316.26 D5.3@1998.33,2316.93
LB13: D5.2 J7.3 | length 509.1
  Top Layer w20: J7.3@1880,1848 J7.3@1890,1848 1890,1948 1923,1981 1923,2168.64 1948,2193.64 1948,2203 1962.9,2217.9 D5.2@1962.9,2316.93
LB14: D5.1 J7.5 | length 525.9
  Top Layer w20: J7.5@1790,1848 1790,2040 1893,2143 1893,2174 1923,2204 1923,2312.46 D5.1@1927.47,2316.93
LB15: D6.3 J7.7 | length 261.6
  Top Layer w20: J7.7@1691,1849 J7.7@1690,1848 1690,1872 1760.43,1942.43 D6.3@1760.43,2079.03
LB16: D6.2 J7.9 | length 320.3
  Top Layer w20: J7.9@1590,1848 1590,1901 1616,1927 1673,1927 1725,1979 D6.2@1725,2079.03
LB17: D6.1 J7.11 | length 386.9
  Top Layer w20: J7.11@1490,1848 1490,1939 1515,1964 1640,1964 1689.57,2013.57 D6.1@1689.57,2079.03
LB18: D7.3 J7.13 | length 162.4
  Top Layer w20: J7.13@1390,1848 1436,1894 D7.3@1436,1991.36
LB19: D7.2 J7.15 | length 205.6
  Top Layer w20: J7.15@1290,1848 1290,1856.43 1343.57,1910 1354.36,1910 1356.36,1912 1373,1912 1400,1939 D7.2@1400,1991.93
LB20: D7.1 J7.17 | length 223.8
  Top Layer w20: J7.17@1190,1848 1190,1856 1269,1935 1344,1935 1364.57,1955.57
LB21: D8.3 J7.19 | length 254.2
  Top Layer w20: J7.19@1100.43,1858.43 J7.19@1090,1848 1090,1925 1110.43,1945.43 D8.3@1110.43,2079.03
LB22: D8.2 J7.21 | length 266.2
  Top Layer w20: J7.21@990,1848 990,1930 1075,2015 D8.2@1075,2079.03
LB23: D8.1 J7.23 | length 265.5
  Top Layer w20: J7.23@890,1848 890,1902 D8.1@1039.57,2051.57
LB24: D9.3 J11.1 | length 647.5
  Top Layer w20: J11.1@453,1959.76 453,1981 569,2097 768,2097 872.53,2201.53 D9.3@872.53,2316.93
LB25: D9.2 J11.3 | length 549.7
  Top Layer w20: J11.3@453,2059.76 515.24,2122 743,2122 837.1,2216.1 D9.2@837.1,2316.93
LB26: D9.1 J11.5 | length 427.4
  Top Layer w20: J11.5@453,2159.76 466.24,2173 681,2173 801.67,2293.67 D9.1@801.67,2316.93
LB27: D10.3 J11.7 | length 587.2
  Top Layer w20: J11.7@453,2259.76 559,2365.76 559,2470 674,2470 785.43,2581.43 D10.3@785.43,2641.93
LB28: D10.2 J11.9 | length 462.6
  Top Layer w20: J11.9@453,2359.76 525,2431.76 525,2479 542,2496 640,2496 750,2606 D10.2@750,2641.93
LB29: D10.1 J11.11 | length 357.9
  Top Layer w20: J11.11@453,2459.76 453,2463 511,2521 626,2521 714.57,2609.57 D10.1@714.57,2641.93
LB30: D11.3 J11.13 | length 719
  Top Layer w20: J11.13@453,2559.76 471.76,2559.76 587,2675 587,2846 632,2891 849,2891 872.53,2914.53 D11.3@872.53,2966.93
LB31: D11.2 J11.15 | length 603.7
  Top Layer w20: J11.15@453,2659.76 556,2762.76 556,2878.64 593.36,2916 828,2916 837.1,2925.1 D11.2@837.1,2966.93
LB32: D11.1 J11.17 | length 473.9
  Top Layer w20: J11.17@453,2759.76 531,2837.76 531,2902.41 550,2921.41 550,2923.29 563,2936.29 563,2937 592.93,2966.93 D11.1@801.67,2966.93
LB33: D12.3 J11.19 | length 1075.1
  Top Layer w20: J11.19@453,2859.76 525,2931.76 525,2933.64 538,2946.64 538,2947.36 582.57,2991.93 608.93,2991.93 638,3021 638,3197 655,3214 937.64,3214 971.21,3180.43 971.21,3116.43 1110.43,3116.43 D12.3@1110.43,3204.83
LB34: D12.2 J11.21 | length 940.9
  Top Layer w20: J11.21@453,2959.76 502.76,2959.76 513,2970 519,2970 613,3064 613,3220 632,3239 948,3239 1006,3181 1006,3149 1075,3149 D12.2@1075,3204.83
LB35: D12.1 J11.23 | length 768.9
  Top Layer w20: J11.23@453,3059.76 516.76,3059.76 587,3130 587,3255 595,3263 620.64,3263 621.64,3264 959,3264 1018.17,3204.83 D12.1@1039.57,3204.83
NetJ6_3: J6.3 R3.1 | length 123.3
  Top Layer w15: R3.1@1147,642.5 1238.5,642.5 J6.3@1261,665
OUT0: J4.2 U1.1 | length 3324.1
  Top Layer w8: U1.1@1476.47,1241.51 1794.51,1241.51 1920,1367 1988,1367
  Top Layer w20: 1988,1367 2488,1367 2488,1500 2530,1542 2724,1542 2770,1588 2770,3073 2760,3083 2760,3089 J4.2@2455.99,3089
OUT1: J4.4 U1.2 | length 3142.4
  Top Layer w8: U1.2@1479.17,1257.39 1790.39,1257.39 1925,1392 1989,1392
  Top Layer w20: 1989,1392 2463,1392 2463,1511 2519,1567 2713.64,1567 2745,1598.36 2745,2965 2721,2989 J4.4@2455.99,2989
OUT2: J4.6 U1.3 | length 2968.1
  Top Layer w8: U1.3@1479.17,1273.13 1779.13,1273.13 1920.64,1414.64 1975.64,1414.64
  Top Layer w20: 1978,1417 2434,1417 2438,1421 2438,1521.36 2508.64,1592 2696,1592 2699.64,1595.64 ; J4.6@2455.99,2889 2704,2889 2720,2873 2720,1608.71 2703.29,1592
OUT3: J4.8 U1.4 | length 2802.4
  Top Layer w8: U1.4@1479.17,1288.88 1769.88,1288.88 1809,1328 1811,1328 1925,1442 1979,1442
  Top Layer w20: 1979,1442 2413,1442 2413,1531.71 2498.29,1617 2557.18,1617 2559,1618.82 2681.82,1618.82 2695,1632 2695,2782 2688,2789 J4.8@2455.99,2789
